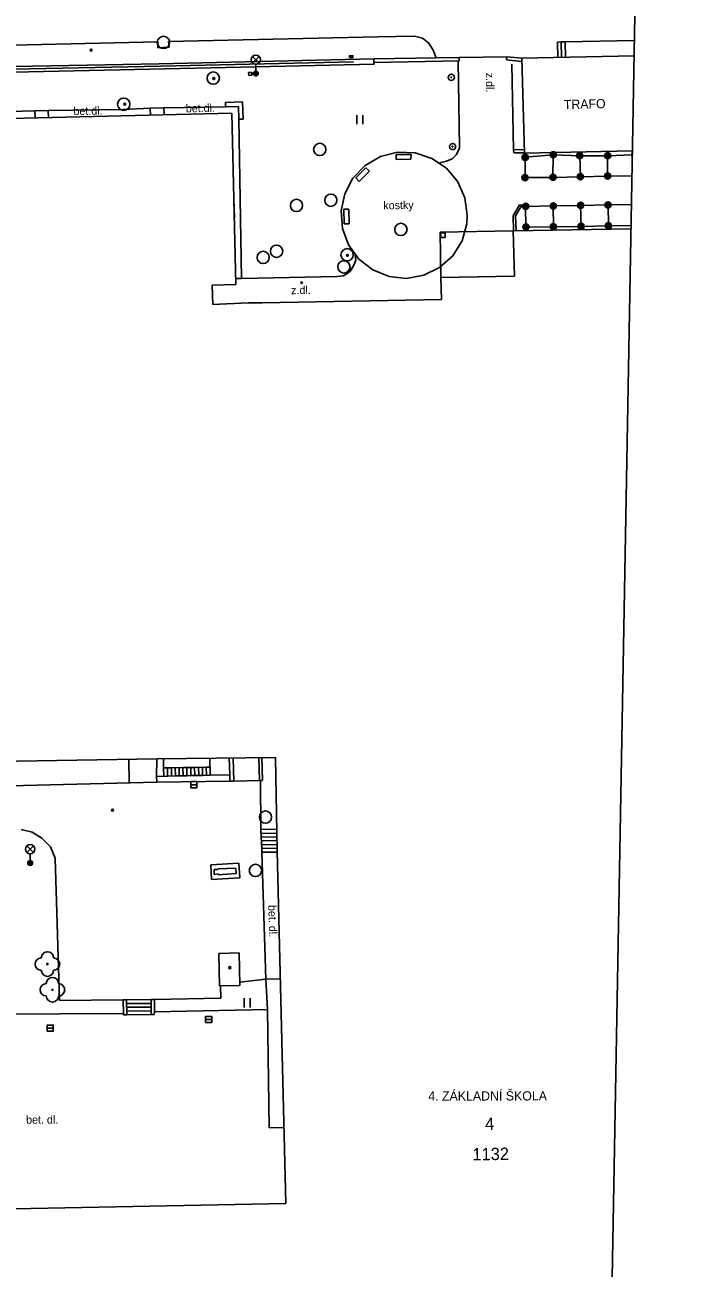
# Model space of a CAD drawing. Extents: x -641829 to -641525, y -1114855 to -1114359.
# Drawn here: x -641580.3 to -641525.3, y -1114772 to -1114670.9 of the extents above; entities that cross this region are included whole.
import ezdxf

# ---------------------------------------------------------------- set-up
doc = ezdxf.new("R2010")
doc.units = 0
for name, color, linetype in [('Vrstva 1', 7, 'Continuous'), ('Vrstva 10', 7, 'Continuous'), ('Vrstva 11', 7, 'Continuous'), ('Vrstva 20', 7, 'Continuous'), ('Vrstva 22', 7, 'Continuous'), ('Vrstva 24', 7, 'Continuous'), ('Vrstva 25', 7, 'Continuous'), ('Vrstva 27', 7, 'Continuous'), ('Vrstva 33', 7, 'Continuous'), ('Vrstva 36', 7, 'Continuous'), ('Vrstva 39', 7, 'Continuous'), ('Vrstva 40', 7, 'Continuous'), ('Vrstva 41', 7, 'Continuous'), ('Vrstva 46', 7, 'Continuous'), ('Vrstva 47', 7, 'Continuous'), ('Vrstva 5', 7, 'Continuous'), ('Vrstva 6', 7, 'Continuous'), ('Vrstva 7', 7, 'Continuous'), ('Vrstva 8', 7, 'Continuous')]:
    doc.layers.add(name, color=color, linetype=linetype)

msp = doc.modelspace()

# ---------------------------------------------------------------- linework, layer by layer
at = {"layer": 'Vrstva 1'}
msp.add_line((-641533.66, -1114832.21), (-641525.3, -1114362.64), dxfattribs=at)
at = {"layer": 'Vrstva 10'}
for p, q in [((-641569.62, -1114732.46), (-641588.99, -1114732.98)), ((-641579.75, -1114736.54), (-641580.62, -1114736.33)), ((-641578.95, -1114737.01), (-641579.75, -1114736.54)), ((-641578.24, -1114737.72), (-641578.95, -1114737.01)), ((-641577.88, -1114738.65), (-641578.24, -1114737.72)), ((-641561.08, -1114738.17), (-641560.75, -1114748.47)), ((-641577.51, -1114750.21), (-641577.88, -1114738.65)), ((-641560.75, -1114748.47), (-641562.87, -1114748.72)), ((-641564.43, -1114749.02), (-641564.42, -1114750.03)), ((-641564.42, -1114750.03), (-641569.81, -1114750.13))]:
    msp.add_line(p, q, dxfattribs=at)
msp.add_lwpolyline([(-641572.34, -1114750.15), (-641577.51, -1114750.21)], dxfattribs=at)
at = {"layer": 'Vrstva 11'}
for p, q in [((-641568.65, -1114672.31), (-641551.65, -1114671.92)), ((-641551.65, -1114671.92), (-641548.66, -1114671.87)), ((-641548.66, -1114671.87), (-641548.01, -1114672.03)), ((-641598.98, -1114672.9), (-641580.14, -1114672.56)), ((-641580.14, -1114672.56), (-641569.53, -1114672.33)), ((-641569.53, -1114672.33), (-641569.52, -1114672.82)), ((-641569.52, -1114672.82), (-641568.61, -1114672.77)), ((-641568.61, -1114672.77), (-641568.65, -1114672.31)), ((-641548.01, -1114672.03), (-641547.5, -1114672.44)), ((-641547.5, -1114672.44), (-641547.15, -1114673)), ((-641537.05, -1114672.34), (-641536.75, -1114672.33)), ((-641537.02, -1114673.6), (-641537.05, -1114672.34)), ((-641536.75, -1114672.33), (-641536.43, -1114672.32)), ((-641536.72, -1114673.59), (-641536.75, -1114672.33)), ((-641530.811, -1114672.211), (-641536.43, -1114672.32)), ((-641536.4, -1114673.59), (-641536.43, -1114672.32)), ((-641569.41, -1114674.12), (-641551.98, -1114673.7)), ((-641551.97, -1114674), (-641551.98, -1114673.7)), ((-641551.97, -1114674), (-641551.95, -1114674.13)), ((-641547.15, -1114673), (-641546.92, -1114673.62)), ((-641545.02, -1114680.9), (-641545.12, -1114673.87)), ((-641545.04, -1114673.59), (-641545.03, -1114673.87)), ((-641541.18, -1114673.53), (-641541.2, -1114673.8)), ((-641541.18, -1114673.53), (-641539.96, -1114673.66)), ((-641594.4, -1114674.59), (-641569.41, -1114674.12)), ((-641561.56, -1114674.35), (-641582.52, -1114674.81)), ((-641551.95, -1114674.13), (-641561.56, -1114674.35)), ((-641540.76, -1114674.13), (-641540.63, -1114681.09)), ((-641579.53, -1114677.93), (-641596.77, -1114678.35)), ((-641579.53, -1114677.93), (-641578.43, -1114677.9)), ((-641579.49, -1114678.49), (-641579.53, -1114677.93)), ((-641572.34, -1114677.81), (-641578.43, -1114677.9)), ((-641578.43, -1114677.9), (-641578.4, -1114678.47)), ((-641570.14, -1114677.72), (-641572.34, -1114677.81)), ((-641570.14, -1114677.72), (-641569.04, -1114677.69)), ((-641570.13, -1114678.27), (-641570.14, -1114677.72)), ((-641564.03, -1114677.61), (-641569.04, -1114677.69)), ((-641569.04, -1114677.69), (-641569.02, -1114678.25)), ((-641564.04, -1114677.26), (-641562.64, -1114677.21)), ((-641564.04, -1114677.26), (-641564.03, -1114677.61)), ((-641564.03, -1114677.61), (-641562.98, -1114677.57)), ((-641562.98, -1114677.57), (-641562.95, -1114678.62)), ((-641562.64, -1114677.21), (-641562.6, -1114678.61)), ((-641562.95, -1114678.62), (-641562.6, -1114678.61)), ((-641562.95, -1114678.62), (-641562.72, -1114691.54)), ((-641545.06, -1114681.11), (-641545.02, -1114680.9)), ((-641539.74, -1114681.07), (-641540.63, -1114681.09)), ((-641550.16, -1114681.47), (-641550.15, -1114681.89)), ((-641550.16, -1114681.47), (-641548.94, -1114681.48)), ((-641550.15, -1114681.89), (-641548.96, -1114681.87)), ((-641548.96, -1114681.87), (-641548.94, -1114681.48)), ((-641546.65, -1114682.15), (-641546.07, -1114682.01)), ((-641546.07, -1114682.01), (-641545.62, -1114681.82)), ((-641545.62, -1114681.82), (-641545.3, -1114681.5)), ((-641545.3, -1114681.5), (-641545.06, -1114681.11)), ((-641540.63, -1114681.09), (-641540.6, -1114681.34)), ((-641540.6, -1114681.34), (-641539.73, -1114681.34)), ((-641539.69, -1114683.36), (-641539.68, -1114681.7)), ((-641539.68, -1114681.7), (-641537.4, -1114681.5)), ((-641537.43, -1114683.34), (-641537.4, -1114681.5)), ((-641537.4, -1114681.5), (-641535.25, -1114681.58)), ((-641535.25, -1114681.58), (-641532.98, -1114681.58)), ((-641535.19, -1114683.29), (-641535.25, -1114681.58)), ((-641532.98, -1114681.58), (-641530.977, -1114681.507)), ((-641532.98, -1114683.23), (-641532.98, -1114681.58)), ((-641553.45, -1114683.37), (-641552.62, -1114682.56)), ((-641553.16, -1114683.67), (-641552.34, -1114682.84)), ((-641552.34, -1114682.84), (-641552.62, -1114682.56)), ((-641553.45, -1114683.37), (-641553.16, -1114683.67)), ((-641537.43, -1114683.34), (-641539.69, -1114683.36)), ((-641535.19, -1114683.29), (-641537.43, -1114683.34)), ((-641532.98, -1114683.23), (-641535.19, -1114683.29)), ((-641531.007, -1114683.212), (-641532.98, -1114683.23)), ((-641554.4, -1114687.11), (-641554.42, -1114685.92)), ((-641554.42, -1114685.92), (-641554.01, -1114685.92)), ((-641553.99, -1114687.1), (-641554.01, -1114685.92)), ((-641540.65, -1114686.46), (-641540.15, -1114685.58)), ((-641539.96, -1114685.6), (-641540.46, -1114686.47)), ((-641540.15, -1114685.58), (-641539.96, -1114685.6)), ((-641539.65, -1114685.69), (-641537.4, -1114685.65)), ((-641539.65, -1114685.69), (-641539.62, -1114687.38)), ((-641537.4, -1114685.65), (-641535.18, -1114685.61)), ((-641537.38, -1114687.35), (-641537.4, -1114685.65)), ((-641535.18, -1114685.61), (-641532.94, -1114685.57)), ((-641535.13, -1114687.32), (-641535.18, -1114685.61)), ((-641532.94, -1114685.57), (-641531.049, -1114685.553)), ((-641532.92, -1114687.26), (-641532.94, -1114685.57)), ((-641553.99, -1114687.1), (-641554.4, -1114687.11)), ((-641540.62, -1114687.68), (-641540.65, -1114686.46)), ((-641540.46, -1114686.47), (-641540.41, -1114687.68)), ((-641546.55, -1114687.84), (-641546.18, -1114687.83)), ((-641546.54, -1114688.23), (-641546.55, -1114687.84)), ((-641546.17, -1114688.22), (-641546.18, -1114687.83)), ((-641532.92, -1114687.26), (-641535.13, -1114687.32)), ((-641531.079, -1114687.244), (-641532.92, -1114687.26)), ((-641546.17, -1114688.22), (-641546.54, -1114688.23)), ((-641553.59, -1114690.48), (-641553.45, -1114690.05)), ((-641553.45, -1114690.05), (-641553.48, -1114689.66)), ((-641554.48, -1114691.34), (-641554.17, -1114691.16)), ((-641554.17, -1114691.16), (-641553.86, -1114690.92)), ((-641553.86, -1114690.92), (-641553.59, -1114690.48)), ((-641554.96, -1114691.39), (-641554.48, -1114691.34)), ((-641565.3, -1114730.52), (-641565.27, -1114731.91)), ((-641563.4, -1114730.5), (-641563.36, -1114732.38)), ((-641561.28, -1114732.34), (-641561.32, -1114730.48)), ((-641561.03, -1114732.33), (-641561.07, -1114730.48)), ((-641571.89, -1114730.61), (-641571.85, -1114732.52)), ((-641569.62, -1114730.57), (-641569.64, -1114732)), ((-641568.75, -1114731.31), (-641568.73, -1114731.98)), ((-641568.43, -1114731.31), (-641568.42, -1114731.98)), ((-641568.12, -1114731.3), (-641568.1, -1114731.97)), ((-641567.8, -1114731.3), (-641567.79, -1114731.96)), ((-641567.49, -1114731.29), (-641567.47, -1114731.96)), ((-641567.17, -1114731.28), (-641567.16, -1114731.95)), ((-641566.86, -1114731.28), (-641566.84, -1114731.94)), ((-641566.54, -1114731.27), (-641566.53, -1114731.94)), ((-641566.23, -1114731.26), (-641566.21, -1114731.93)), ((-641565.91, -1114731.26), (-641565.9, -1114731.93)), ((-641565.6, -1114731.25), (-641565.58, -1114731.92)), ((-641569.62, -1114732.46), (-641563.68, -1114732.38)), ((-641563.68, -1114732.38), (-641563.36, -1114732.38)), ((-641561.28, -1114732.34), (-641563.36, -1114732.38)), ((-641561.28, -1114732.34), (-641561.18, -1114732.34)), ((-641561.18, -1114732.34), (-641561.03, -1114732.33)), ((-641561.18, -1114732.34), (-641561.15, -1114736.33)), ((-641559.87, -1114736.3), (-641561.15, -1114736.33)), ((-641559.86, -1114736.61), (-641561.14, -1114736.64)), ((-641559.85, -1114736.92), (-641561.13, -1114736.94)), ((-641559.85, -1114737.22), (-641561.12, -1114737.25)), ((-641559.84, -1114737.53), (-641561.1, -1114737.56)), ((-641559.83, -1114737.84), (-641561.09, -1114737.86)), ((-641559.83, -1114738.15), (-641561.08, -1114738.17)), ((-641562.94, -1114739.05), (-641565.23, -1114739.18)), ((-641565.16, -1114740.38), (-641565.23, -1114739.18)), ((-641564.64, -1114739.57), (-641564.96, -1114739.57)), ((-641564.96, -1114739.57), (-641564.96, -1114739.96)), ((-641563.19, -1114739.46), (-641564.64, -1114739.51)), ((-641564.64, -1114739.51), (-641564.64, -1114739.57)), ((-641563.19, -1114739.46), (-641563.17, -1114739.9)), ((-641562.87, -1114740.25), (-641562.94, -1114739.05)), ((-641565.16, -1114740.38), (-641562.87, -1114740.25)), ((-641564.96, -1114739.96), (-641564.6, -1114739.92)), ((-641564.63, -1114740), (-641563.17, -1114739.9)), ((-641564.6, -1114739.92), (-641564.63, -1114740)), ((-641559.58, -1114748.44), (-641560.75, -1114748.47)), ((-641560.75, -1114748.47), (-641560.61, -1114750.95)), ((-641572.34, -1114750.15), (-641572.07, -1114750.15)), ((-641572.07, -1114750.15), (-641570.07, -1114750.13)), ((-641572.07, -1114750.46), (-641570.07, -1114750.44)), ((-641572.07, -1114750.76), (-641570.06, -1114750.74)), ((-641569.81, -1114750.13), (-641570.07, -1114750.13)), ((-641569.79, -1114751.13), (-641569.81, -1114750.13)), ((-641572.32, -1114751.27), (-641593.17, -1114751.37)), ((-641572.06, -1114751.37), (-641572.32, -1114751.38)), ((-641572.06, -1114751.07), (-641570.06, -1114751.05)), ((-641572.06, -1114751.37), (-641570.06, -1114751.35)), ((-641569.82, -1114751.35), (-641570.06, -1114751.35)), ((-641569.79, -1114751.13), (-641569.82, -1114751.35)), ((-641560.61, -1114750.95), (-641569.79, -1114751.13)), ((-641560.61, -1114750.95), (-641560.47, -1114760.55)), ((-641559.29, -1114760.52), (-641560.47, -1114760.55))]:
    msp.add_line(p, q, dxfattribs=at)
for points in [[(-641551.98, -1114673.7), (-641546.92, -1114673.62), (-641545.04, -1114673.59)], [(-641544.38, -1114686.41), (-641544.58, -1114684.99), (-641545.16, -1114683.69), (-641546.08, -1114682.59), (-641547.26, -1114681.79), (-641548.62, -1114681.35), (-641550.05, -1114681.3), (-641551.44, -1114681.65), (-641552.67, -1114682.36), (-641553.67, -1114683.39), (-641554.34, -1114684.66), (-641554.63, -1114686.06), (-641554.53, -1114687.48), (-641554.04, -1114688.82), (-641553.2, -1114689.98), (-641552.07, -1114690.86), (-641550.74, -1114691.39), (-641549.32, -1114691.54), (-641547.91, -1114691.28), (-641546.63, -1114690.66), (-641545.57, -1114689.7), (-641544.81, -1114688.48), (-641544.43, -1114687.11), (-641544.38, -1114686.41)], [(-641539.62, -1114687.38), (-641537.38, -1114687.35), (-641535.13, -1114687.32)], [(-641563.19, -1114691.55), (-641562.72, -1114691.54), (-641554.96, -1114691.39)], [(-641569.08, -1114730.56), (-641569.06, -1114731.32), (-641569.05, -1114731.99)], [(-641563.72, -1114730.5), (-641563.69, -1114731.88), (-641563.68, -1114732.38)], [(-641565.28, -1114731.24), (-641565.6, -1114731.25), (-641566.54, -1114731.27), (-641567.49, -1114731.29), (-641568.43, -1114731.31), (-641569.06, -1114731.32)], [(-641561.15, -1114736.33), (-641561.13, -1114736.94), (-641561.09, -1114737.86), (-641561.08, -1114738.17)], [(-641572.34, -1114750.15), (-641572.32, -1114751.27), (-641572.32, -1114751.38)], [(-641572.07, -1114750.15), (-641572.07, -1114750.46), (-641572.06, -1114751.07), (-641572.06, -1114751.37)], [(-641570.06, -1114751.35), (-641570.06, -1114751.05), (-641570.07, -1114750.13)]]:
    msp.add_lwpolyline(points, dxfattribs=at)
at = {"layer": 'Vrstva 20'}
for centre, radius in [((-641574.95, -1114673), 0.075), ((-641574.95, -1114673), 0.0204), ((-641564.98, -1114675.31), 0.075), ((-641564.98, -1114675.31), 0.0204), ((-641572.22, -1114677.39), 0.075), ((-641572.22, -1114677.39), 0.0204), ((-641554.12, -1114689.67), 0.075), ((-641554.12, -1114689.67), 0.0204), ((-641557.84, -1114691.89), 0.075), ((-641557.84, -1114691.89), 0.0204), ((-641573.21, -1114734.75), 0.075), ((-641573.21, -1114734.75), 0.0204)]:
    msp.add_circle(centre, radius, dxfattribs=at)
at = {"layer": 'Vrstva 22'}
for centre in [(-641578.5, -1114747.25), (-641578.09, -1114749.34)]:
    msp.add_circle(centre, 0.05, dxfattribs=at)
for centre, start, end in [((-641578.5, -1114746.75), 0, 180), ((-641579, -1114747.25), 90, 270), ((-641578, -1114747.25), 270, 90), ((-641578.5, -1114747.75), 180, 0), ((-641578.09, -1114748.84), 0, 180), ((-641578.59, -1114749.34), 90, 270), ((-641577.59, -1114749.34), 270, 90), ((-641578.09, -1114749.84), 180, 0)]:
    msp.add_arc(centre, 0.5, start, end, dxfattribs=at)
at = {"layer": 'Vrstva 24'}
for points in [[(-641553.96, -1114673.61), (-641553.96, -1114673.45), (-641553.68, -1114673.45), (-641553.68, -1114673.61), (-641553.96, -1114673.61)], [(-641562.15, -1114674.81), (-641561.89, -1114674.81), (-641561.9, -1114675.04), (-641562.14, -1114675.05), (-641562.15, -1114674.81)]]:
    msp.add_lwpolyline(points, dxfattribs=at)
at = {"layer": 'Vrstva 25'}
msp.add_line((-641530.979, -1114681.637), (-641530.974, -1114681.356), dxfattribs=at)
for centre, radius in [((-641545.68, -1114675.21), 0.25), ((-641545.68, -1114675.21), 0.0303), ((-641545.58, -1114680.83), 0.25), ((-641545.58, -1114680.83), 0.0303), ((-641539.68, -1114681.7), 0.25), ((-641539.68, -1114681.7), 0.2), ((-641539.68, -1114681.7), 0.15), ((-641539.68, -1114681.7), 0.1), ((-641539.68, -1114681.7), 0.05), ((-641537.4, -1114681.5), 0.25), ((-641537.4, -1114681.5), 0.2), ((-641537.4, -1114681.5), 0.15), ((-641537.4, -1114681.5), 0.1), ((-641537.4, -1114681.5), 0.05), ((-641535.25, -1114681.58), 0.25), ((-641535.25, -1114681.58), 0.2), ((-641535.25, -1114681.58), 0.15), ((-641535.25, -1114681.58), 0.1), ((-641535.25, -1114681.58), 0.05), ((-641532.98, -1114681.58), 0.25), ((-641532.98, -1114681.58), 0.2), ((-641532.98, -1114681.58), 0.15), ((-641532.98, -1114681.58), 0.1), ((-641532.98, -1114681.58), 0.05), ((-641537.43, -1114683.34), 0.25), ((-641535.19, -1114683.29), 0.25), ((-641535.19, -1114683.29), 0.2), ((-641532.98, -1114683.23), 0.25), ((-641532.98, -1114683.23), 0.2), ((-641532.98, -1114683.23), 0.15), ((-641539.69, -1114683.36), 0.25), ((-641539.69, -1114683.36), 0.2), ((-641539.69, -1114683.36), 0.15), ((-641539.69, -1114683.36), 0.1), ((-641539.69, -1114683.36), 0.05), ((-641537.43, -1114683.34), 0.2), ((-641537.43, -1114683.34), 0.15), ((-641537.43, -1114683.34), 0.1), ((-641537.43, -1114683.34), 0.05), ((-641535.19, -1114683.29), 0.15), ((-641535.19, -1114683.29), 0.1), ((-641535.19, -1114683.29), 0.05), ((-641532.98, -1114683.23), 0.1), ((-641532.98, -1114683.23), 0.05), ((-641539.65, -1114685.69), 0.25), ((-641539.65, -1114685.69), 0.2), ((-641539.65, -1114685.69), 0.15), ((-641539.65, -1114685.69), 0.1), ((-641539.65, -1114685.69), 0.05), ((-641537.4, -1114685.65), 0.25), ((-641537.4, -1114685.65), 0.2), ((-641537.4, -1114685.65), 0.15), ((-641537.4, -1114685.65), 0.1), ((-641537.4, -1114685.65), 0.05), ((-641535.18, -1114685.61), 0.25), ((-641535.18, -1114685.61), 0.2), ((-641535.18, -1114685.61), 0.15), ((-641535.18, -1114685.61), 0.1), ((-641535.18, -1114685.61), 0.05), ((-641532.94, -1114685.57), 0.25), ((-641532.94, -1114685.57), 0.2), ((-641532.94, -1114685.57), 0.15), ((-641532.94, -1114685.57), 0.1), ((-641532.94, -1114685.57), 0.05), ((-641539.62, -1114687.38), 0.25), ((-641537.38, -1114687.35), 0.25), ((-641535.13, -1114687.32), 0.25), ((-641535.13, -1114687.32), 0.2), ((-641532.92, -1114687.26), 0.25), ((-641532.92, -1114687.26), 0.2), ((-641532.92, -1114687.26), 0.15), ((-641539.62, -1114687.38), 0.2), ((-641539.62, -1114687.38), 0.15), ((-641539.62, -1114687.38), 0.1), ((-641539.62, -1114687.38), 0.05), ((-641537.38, -1114687.35), 0.2), ((-641537.38, -1114687.35), 0.15), ((-641537.38, -1114687.35), 0.1), ((-641537.38, -1114687.35), 0.05), ((-641535.13, -1114687.32), 0.15), ((-641535.13, -1114687.32), 0.1), ((-641535.13, -1114687.32), 0.05), ((-641532.92, -1114687.26), 0.1), ((-641532.92, -1114687.26), 0.05)]:
    msp.add_circle(centre, radius, dxfattribs=at)
msp.add_arc((-641530.77, -1114681.5), 0.25, 144.79155, 213.16853, dxfattribs=at)
at = {"layer": 'Vrstva 27'}
for p, q in [((-641566.86, -1114732.68), (-641566.36, -1114732.68)), ((-641565.65, -1114751.75), (-641565.15, -1114751.75)), ((-641578.52, -1114752.46), (-641578.02, -1114752.46))]:
    msp.add_line(p, q, dxfattribs=at)
for points in [[(-641566.86, -1114732.93), (-641566.36, -1114732.93), (-641566.36, -1114732.43), (-641566.86, -1114732.43)], [(-641565.65, -1114752), (-641565.15, -1114752), (-641565.15, -1114751.5), (-641565.65, -1114751.5)], [(-641578.52, -1114752.71), (-641578.02, -1114752.71), (-641578.02, -1114752.21), (-641578.52, -1114752.21)]]:
    msp.add_lwpolyline(points, close=True, dxfattribs=at)
for centre in [(-641569.07, -1114672.37), (-641565.02, -1114675.27), (-641572.3, -1114677.4), (-641556.37, -1114681.07), (-641555.47, -1114685.19), (-641558.26, -1114685.62), (-641549.78, -1114687.57), (-641559.88, -1114689.34), (-641554.15, -1114689.62), (-641560.97, -1114689.84), (-641554.41, -1114690.61), (-641560.78, -1114735.31), (-641561.6, -1114739.64)]:
    msp.add_circle(centre, 0.5, dxfattribs=at)
at = {"layer": 'Vrstva 33'}
for p, q in [((-641561.835, -1114674.04), (-641561.305, -1114673.51)), ((-641561.835, -1114673.51), (-641561.305, -1114674.04)), ((-641561.57, -1114674.15), (-641561.57, -1114674.9)), ((-641580.165, -1114738.18), (-641579.635, -1114737.65)), ((-641580.165, -1114737.65), (-641579.635, -1114738.18)), ((-641579.9, -1114738.29), (-641579.9, -1114739.04))]:
    msp.add_line(p, q, dxfattribs=at)
for centre, radius in [((-641561.57, -1114673.775), 0.375), ((-641561.57, -1114674.9), 0.2), ((-641561.57, -1114674.9), 0.145), ((-641561.57, -1114674.9), 0.0876), ((-641579.9, -1114737.915), 0.375), ((-641579.9, -1114739.04), 0.2), ((-641579.9, -1114739.04), 0.145), ((-641579.9, -1114739.04), 0.0876)]:
    msp.add_circle(centre, radius, dxfattribs=at)
at = {"layer": 'Vrstva 36'}
for p, q in [((-641553.364, -1114679.023), (-641553.364, -1114678.273)), ((-641552.864, -1114679.023), (-641552.864, -1114678.273)), ((-641562.514, -1114750.773), (-641562.514, -1114750.023)), ((-641562.014, -1114750.773), (-641562.014, -1114750.023))]:
    msp.add_line(p, q, dxfattribs=at)
at = {"layer": 'Vrstva 39'}
for radius in [0.09, 0.0398]:
    msp.add_circle((-641563.68, -1114747.55), radius, dxfattribs=at)
at = {"layer": 'Vrstva 5'}
for p, q in [((-641539.96, -1114673.66), (-641530.834, -1114673.472)), ((-641539.96, -1114673.66), (-641539.73, -1114681.36)), ((-641599.83, -1114678.97), (-641563.52, -1114678.12)), ((-641563.52, -1114678.12), (-641563.18, -1114692.04)), ((-641539.73, -1114681.36), (-641530.971, -1114681.186)), ((-641546.58, -1114687.78), (-641540.66, -1114687.68)), ((-641546.52, -1114691.47), (-641546.58, -1114687.78)), ((-641540.66, -1114687.68), (-641531.084, -1114687.52)), ((-641540.66, -1114687.68), (-641540.55, -1114691.37)), ((-641565.11, -1114692.09), (-641563.18, -1114692.04)), ((-641565.07, -1114693.67), (-641565.11, -1114692.09)), ((-641546.52, -1114691.47), (-641540.55, -1114691.37)), ((-641546.49, -1114693.26), (-641546.52, -1114691.47)), ((-641565.07, -1114693.67), (-641562.19, -1114693.53)), ((-641561.05, -1114693.52), (-641546.49, -1114693.26)), ((-641559.98, -1114730.46), (-641569.62, -1114730.57)), ((-641559.98, -1114730.46), (-641559.83, -1114738.06)), ((-641569.62, -1114730.57), (-641588.52, -1114730.89)), ((-641559.83, -1114738.06), (-641559.14, -1114766.7)), ((-641564.58, -1114746.38), (-641562.93, -1114746.34)), ((-641564.58, -1114746.38), (-641564.52, -1114749.03)), ((-641562.87, -1114748.99), (-641562.93, -1114746.34)), ((-641564.52, -1114749.03), (-641562.87, -1114748.99)), ((-641559.14, -1114766.7), (-641603.05, -1114767.54))]:
    msp.add_line(p, q, dxfattribs=at)
at = {"layer": 'Vrstva 6'}
for p, q in [((-641563.31, -1114686.62), (-641563.35, -1114685.14)), ((-641542.3, -1114691.4), (-641544.58, -1114691.44)), ((-641563.99, -1114693.62), (-641565.07, -1114693.67))]:
    msp.add_line(p, q, dxfattribs=at)
at = {"layer": 'Vrstva 7'}
for p, q in [((-641569.31, -1114674.3), (-641553.63, -1114673.96)), ((-641551.97, -1114674), (-641545.03, -1114673.87)), ((-641541.2, -1114673.8), (-641539.95, -1114673.93)), ((-641592.94, -1114674.79), (-641569.31, -1114674.3)), ((-641569.64, -1114732), (-641569.62, -1114732.46))]:
    msp.add_line(p, q, dxfattribs=at)
msp.add_lwpolyline([(-641563.69, -1114731.88), (-641565.27, -1114731.91), (-641565.9, -1114731.93), (-641566.21, -1114731.93), (-641566.84, -1114731.94), (-641567.16, -1114731.95), (-641567.79, -1114731.96), (-641568.1, -1114731.97), (-641568.73, -1114731.98), (-641569.64, -1114732)], dxfattribs=at)
at = {"layer": 'Vrstva 8'}
for p, q in [((-641541.18, -1114673.53), (-641545.04, -1114673.59)), ((-641561.05, -1114693.52), (-641562.19, -1114693.53))]:
    msp.add_line(p, q, dxfattribs=at)

# ---------------------------------------------------------------- texts
at = {"layer": 'Vrstva 40'}
for s, height, rotation, p in [('z.dl.', 0.6499, 270.78259, (-641542.87, -1114674.84)), ('bet.dl.', 0.65, 1.34102, (-641576.38, -1114678.28)), ('bet.dl.', 0.65, 1.34102, (-641567.25, -1114678.06)), ('kostky', 0.65, 0.96286, (-641551.2, -1114685.94)), ('z.dl.', 0.6499, 1.02303, (-641558.69, -1114692.83)), ('bet. dl.', 0.65, 271.83506, (-641560.56, -1114742.46)), ('bet. dl.', 0.6499, 0.27205, (-641580.23, -1114760.22))]:
    msp.add_text(s, height=height, rotation=rotation, dxfattribs=at).set_placement(p)
at = {"layer": 'Vrstva 41'}
for s, rotation, p in [('TRAFO', 1.46461, (-641536.53, -1114677.8)), ('4. ZÁKLADNÍ ŠKOLA', 0.0594, (-641547.551, -1114758.341))]:
    msp.add_text(s, height=0.75, rotation=rotation, dxfattribs=at).set_placement(p)
at = {"layer": 'Vrstva 46'}
msp.add_text('4', height=1, rotation=0.94435, dxfattribs=at).set_placement((-641542.93, -1114760.726))
at = {"layer": 'Vrstva 47'}
msp.add_text('1132', height=1, rotation=0.94435, dxfattribs=at).set_placement((-641543.963, -1114763.203))

doc.saveas('drawing.dxf')
